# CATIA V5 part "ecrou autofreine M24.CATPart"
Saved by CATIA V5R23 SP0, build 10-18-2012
Part number: ecrou autofreine M24
Bounding box of the stored display mesh (mm): x -18.574 to 18.574, y 0 to 10, z -18.574 to 18.574
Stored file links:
  C:\wamp\www\COURS\CONCEPTION GMP1\TITRE 01-CATIA VOLUMIQUE\05--ACTIONNEUR DE VANNE\prof\CORRECTION\Assemblage\ecrou autofreine M24.CATPart
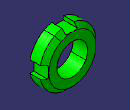
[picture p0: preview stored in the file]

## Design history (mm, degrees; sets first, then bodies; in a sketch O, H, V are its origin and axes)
Body1 (main body)
  Sketch1 on yz-plane, origin (0, 0, 0), H (0, 1, 0), V (0, 0, 1)
    line L1 (0, 0) -> (0, 19)
    line L2 (0, 19) -> (7, 19)
    point P2 (7, 19)
    line L3 (7, 19) -> (10, 16)
    line L4 (10, 16) -> (10, 0)
    point P4 (10, 0)
    axis line L5 (0, 0) -> (57.3791, 0)
    distance L1 L4 = 10
    angle L3 L2 = 45
    distance P2 L5 = 19
    distance P2 L1 = 7
    vertical: L1 V, L4 V
    horizontal: L2 H, L5 H
    coincidence: P4 H
  Shaft1: profile Sketch1, axis Sketch1.L5, angle 360
  Sketch2 on face of Shaft1 from Sketch1.L4, origin (0, 10, 0), H (1, 0, 0), V (0, 0, -1)
    point P1 (0, 0)
    coincidence: P1 V, P1 H
  Hole1: placed by Sketch2, at (0, 10, 0) direction (0, -1, 0), diameter 20.752, depth 10, threaded "M24", thread diameter 24, thread depth 10, pitch 3
  Sketch3 on face of Shaft1 from Sketch1.L4, origin (0, 10, 0), H (-1, 0, 0), V (0, 0, 1)
    line L1 (-4, 19) -> (4, 19)
    line L2 (4, 19) -> (4, 16)
    line L3 (4, 16) -> (-4, 16)
    line L4 (-4, 16) -> (-4, 19)
    axis line L5 (0, 0) -> (0, 32.3606)
    reference projected circle E1 centre (0, 0) radius 19 from edge [face of Shaft1 from Sketch1.L2 | face of Shaft1 from Sketch1.L3]
    distance L4 L2 = 8
    distance L3 L1 = 3
    horizontal: L1 H, L3 H
    vertical: L2 V, L4 V, L5 V
    symmetry: L4 L2 L5
    tangency: E1 L1
  Pocket1: profile Sketch3, direction (0, -1, 0), through (limit type 3)
  CircPattern1: of Pocket1, instances 4, angular step 90 {= 360.0*1 deg/CircPattern1.AngularNumber}, axis from Y axis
